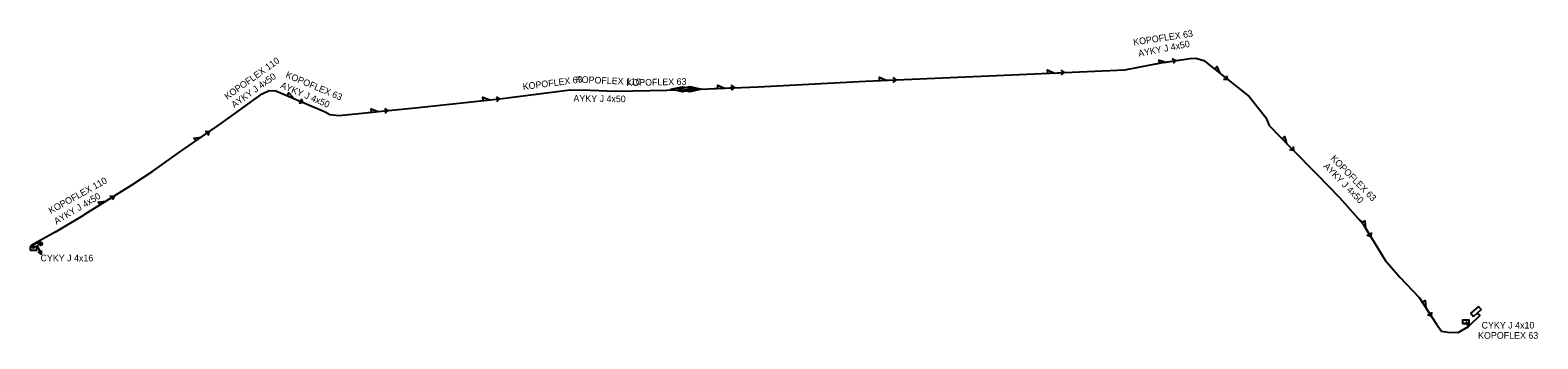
# Model space of a CAD drawing. Extents: x -621441 to -621214, y -1123352 to -1123305.
import ezdxf

# ---------------------------------------------------------------- set-up
doc = ezdxf.new("R2010")
doc.units = 0
for name, color, linetype in [('Vrstva 24', 7, 'Continuous'), ('Vrstva 25', 7, 'Continuous'), ('Vrstva 26', 7, 'Continuous'), ('Vrstva 32', 7, 'Continuous'), ('Vrstva 42', 7, 'Continuous'), ('Vrstva 50', 7, 'Continuous'), ('Vrstva 51', 7, 'Continuous')]:
    doc.layers.add(name, color=color, linetype=linetype)

msp = doc.modelspace()

# ---------------------------------------------------------------- linework, layer by layer
at = {"layer": 'Vrstva 24'}
for points in [[(-621441.2, -1123338.64), (-621440.2, -1123338.64), (-621440.2, -1123338.14), (-621441.2, -1123338.14)], [(-621225.3, -1123349.68), (-621224.3, -1123349.68), (-621224.3, -1123349.18), (-621225.3, -1123349.18)]]:
    msp.add_lwpolyline(points, close=True, dxfattribs=at)
at = {"layer": 'Vrstva 25'}
for points in [[(-621222.9, -1123347.13), (-621224.03, -1123348.09), (-621223.64, -1123348.6)], [(-621223.64, -1123348.6), (-621222.5, -1123347.58), (-621222.9, -1123347.13)]]:
    msp.add_lwpolyline(points, dxfattribs=at)
at = {"layer": 'Vrstva 26'}
for radius in [0.25, 0.15, 0.075]:
    msp.add_circle((-621439.63, -1123337.66), radius, dxfattribs=at)
at = {"layer": 'Vrstva 32'}
for points in [[(-621344.62, -1123314.37), (-621342.87, -1123313.982), (-621341.12, -1123314.37), (-621342.87, -1123314.758), (-621344.62, -1123314.37)], [(-621343.5, -1123314.34), (-621341.75, -1123313.952), (-621340, -1123314.34), (-621341.75, -1123314.728), (-621343.5, -1123314.34)]]:
    msp.add_lwpolyline(points, dxfattribs=at)
at = {"layer": 'Vrstva 42'}
msp.add_line((-621440.17, -1123337.84), (-621439.549, -1123339.206), dxfattribs=at)
msp.add_lwpolyline([(-621439.529, -1123338.647), (-621439.549, -1123339.206), (-621439.984, -1123338.854)], dxfattribs=at)
at = {"layer": 'Vrstva 50'}
for points in [[(-621437.45, -1123335.92), (-621433.08, -1123333.3), (-621432.95, -1123333.19), (-621425.91, -1123328.82), (-621422.69, -1123326.7), (-621418.85, -1123323.95), (-621412.38, -1123319.46), (-621406.22, -1123315.05), (-621405.15, -1123314.55), (-621404.18, -1123314.61), (-621396.75, -1123317.75), (-621396.03, -1123318.19), (-621394.66, -1123318.33), (-621382.67, -1123317.1), (-621370.44, -1123315.81), (-621359.8, -1123314.46), (-621356.8, -1123314.49), (-621352.89, -1123314.65), (-621342.68, -1123314.43), (-621331.47, -1123313.98), (-621315.27, -1123313.14), (-621293.22, -1123312.2), (-621276.17, -1123311.44), (-621270.75, -1123310.38), (-621266.32, -1123309.72), (-621265.47, -1123309.66), (-621264.28, -1123310.03), (-621257.45, -1123315.47), (-621254.91, -1123318.64), (-621254.44, -1123319.82), (-621251.07, -1123323.29), (-621247.27, -1123327.15), (-621243.82, -1123330.66), (-621240.28, -1123334.72), (-621236.93, -1123340.13), (-621234.74, -1123342.67), (-621231.8, -1123345.73), (-621229.21, -1123349.79), (-621228.45, -1123350.83), (-621227.52, -1123351)], [(-621437.45, -1123335.92), (-621440.57, -1123337.64)], [(-621440.57, -1123337.64), (-621441.06, -1123337.92), (-621440.8, -1123338.39)], [(-621439.88, -1123337.83), (-621440.09, -1123337.5), (-621440.86, -1123337.92), (-621440.6, -1123338.39)], [(-621223.07, -1123348.09), (-621222.68, -1123348.47), (-621224.34, -1123350.09), (-621224.75, -1123349.42)], [(-621227.52, -1123351), (-621225.96, -1123351.01), (-621224.39, -1123350.13), (-621224.83, -1123349.46)]]:
    msp.add_lwpolyline(points, dxfattribs=at)
at = {"layer": 'Vrstva 51'}
for points in [[(-621288.307, -1123311.98), (-621287.808, -1123311.959), (-621287.829, -1123311.459), (-621286.809, -1123311.915), (-621285.31, -1123311.85)], [(-621285.826, -1123311.497), (-621285.31, -1123311.85), (-621285.793, -1123312.246)], [(-621271.44, -1123310.53), (-621270.946, -1123310.448), (-621271.028, -1123309.955), (-621269.96, -1123310.285), (-621268.48, -1123310.04)], [(-621269.035, -1123309.752), (-621268.48, -1123310.04), (-621268.912, -1123310.492)], [(-621263.036, -1123311.021), (-621262.645, -1123311.332), (-621262.334, -1123310.941), (-621261.863, -1123311.955), (-621260.69, -1123312.89)], [(-621338.037, -1123314.243), (-621337.538, -1123314.222), (-621337.558, -1123313.723), (-621336.539, -1123314.181), (-621335.04, -1123314.12)], [(-621335.555, -1123313.766), (-621335.04, -1123314.12), (-621335.524, -1123314.515)], [(-621313.657, -1123313.072), (-621313.158, -1123313.05), (-621313.18, -1123312.551), (-621312.159, -1123313.006), (-621310.66, -1123312.94)], [(-621311.176, -1123312.587), (-621310.66, -1123312.94), (-621311.143, -1123313.337)], [(-621260.847, -1123312.285), (-621260.69, -1123312.89), (-621261.315, -1123312.872)], [(-621402.845, -1123315.176), (-621402.384, -1123315.37), (-621402.19, -1123314.909), (-621401.462, -1123315.758), (-621400.08, -1123316.34)], [(-621400.395, -1123315.8), (-621400.08, -1123316.34), (-621400.686, -1123316.492)], [(-621373.423, -1123316.125), (-621372.926, -1123316.072), (-621372.979, -1123315.575), (-621371.932, -1123315.967), (-621370.44, -1123315.81)], [(-621370.977, -1123315.49), (-621370.44, -1123315.81), (-621370.898, -1123316.235)], [(-621390.244, -1123317.877), (-621389.747, -1123317.826), (-621389.798, -1123317.328), (-621388.752, -1123317.723), (-621387.26, -1123317.57)], [(-621387.796, -1123317.248), (-621387.26, -1123317.57), (-621387.719, -1123317.994)], [(-621416.658, -1123322.439), (-621416.249, -1123322.153), (-621416.535, -1123321.743), (-621415.429, -1123321.58), (-621414.2, -1123320.72)], [(-621414.825, -1123320.699), (-621414.2, -1123320.72), (-621414.395, -1123321.314)], [(-621252.844, -1123321.462), (-621252.495, -1123321.82), (-621252.137, -1123321.471), (-621251.797, -1123322.536), (-621250.75, -1123323.61)], [(-621250.831, -1123322.99), (-621250.75, -1123323.61), (-621251.368, -1123323.514)], [(-621431.094, -1123332.05), (-621430.67, -1123331.785), (-621430.935, -1123331.361), (-621429.822, -1123331.255), (-621428.55, -1123330.46)], [(-621429.173, -1123330.407), (-621428.55, -1123330.46), (-621428.775, -1123331.043)], [(-621240.701, -1123334.041), (-621240.438, -1123334.466), (-621240.013, -1123334.202), (-621239.911, -1123335.315), (-621239.12, -1123336.59)], [(-621239.065, -1123335.967), (-621239.12, -1123336.59), (-621239.702, -1123336.363)], [(-621231.601, -1123346.039), (-621231.333, -1123346.461), (-621230.911, -1123346.193), (-621230.796, -1123347.305), (-621229.99, -1123348.57)], [(-621229.942, -1123347.947), (-621229.99, -1123348.57), (-621230.575, -1123348.35)]]:
    msp.add_lwpolyline(points, dxfattribs=at)

# ---------------------------------------------------------------- texts
at = {"layer": 'Vrstva 42'}
for s, rotation, p in [('KOPOFLEX 63', 8.47386, (-621274.84, -1123307.76)), ('AYKY J 4x50', 11.06577, (-621274.07, -1123309.48)), ('KOPOFLEX 110', 35.59923, (-621411.48, -1123315.98)), ('KOPOFLEX 63', 337.0905, (-621402.78, -1123312.55)), ('AYKY J 4x50', 35.59923, (-621410.43, -1123317.23)), ('AYKY J 4x50', 337.0905, (-621403.57, -1123314.13)), ('KOPOFLEX 63', 7.23105, (-621366.88, -1123314.47)), ('KOPOFLEX 110', 357.65676, (-621358.97, -1123313.36)), ('KOPOFLEX 63', 1.23435, (-621351.32, -1123313.88)), ('AYKY J 4x50', 359.42706, (-621359.31, -1123316.24)), ('KOPOFLEX 63', 314.55126, (-621245.25, -1123324.88)), ('KOPOFLEX 110', 28.86714, (-621438.09, -1123333.17)), ('AYKY J 4x50', 314.55126, (-621246.32, -1123326.05)), ('AYKY J 4x50', 30.94443, (-621437.24, -1123334.79))]:
    msp.add_text(s, height=1, rotation=rotation, dxfattribs=at).set_placement(p)
for s, p in [('CYKY J 4x16', (-621439.64, -1123340.3)), ('CYKY J 4x10', (-621222.41, -1123350.43)), ('KOPOFLEX 63', (-621222.94, -1123351.97))]:
    msp.add_text(s, height=1, dxfattribs=at).set_placement(p)

doc.saveas('drawing.dxf')
